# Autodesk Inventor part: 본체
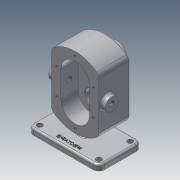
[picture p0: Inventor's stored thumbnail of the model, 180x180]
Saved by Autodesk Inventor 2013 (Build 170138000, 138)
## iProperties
Created: 2019-03
Part Number: 본체
Material: 알루미늄 6061
Document SubType Name: Modeling
Designer: Administrator
Density: 2.71 g/cm^3
Mass: 1191.13 g
Surface Area: 720.144 cm^2
Volume: 439.532 cm^3
Author: Administrator
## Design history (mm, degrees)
sketch "스케치1"
  geometry: L1 (-40, 44.721)-(-40, -44.721); L2 (40, 44.721)-(40, -44.721); A1 r 60 centre (0, 0) between (-40, -44.721) and (40, -44.721); A2 r 60 centre (0, 0) between (40, 44.721) and (-40, 44.721); 1 further point
  constraints: 4 end point, 4 point on circle, 2 centre point, 1 coincident, 1 parallel, 1 vertical
  dimensions: "d1" = 40 distance from line of A1.centre L1; "d2" = 40 distance from line of L2 point (0, 0); "d3" = 60 radius of A2; "d4" = 60 radius of A1
extrude "돌출1" new body sketch "스케치1" stored distance "d5" = 53; taper "d6" = 0 deg
sketch "스케치2"
  geometry: L1 (40, -44.721)-(40, 44.721) reference; L2 (0, 0)-(0, 78); L3 (60, 68)-(-60, 68); L4 (-60, 68)-(-60, 78); L5 (-60, 78)-(60, 78); L6 (60, 78)-(60, 68); A1 r 60 centre (0, 0) between (40, 44.721) and (-40, 44.721) reference
  constraints: 10 end point, 3 parallel, 1 horizontal, 1 midpoint, 1 perpendicular
  dimensions: "d7" = 78 distance of L2.end L2.start; "d8" = 120 distance of L4.end L5.end; "d9" = 10 distance of L3.end L4.end
extrude "돌출2" join sketch "스케치2" distance "d10" = 73; taper "d11" = 0 deg
sketch "스케치3"
  geometry: L1 (120, 0)-(0, 0) reference; L2 (54, 0)-(66, 0); L3 (66, 0)-(66, -43); L4 (66, -43)-(54, -43); L5 (54, -43)-(54, 0); 2 further points
  constraints: 8 end point, 2 midpoint, 2 parallel, 1 horizontal, 1 perpendicular
  dimensions: "d12" = 12 distance of L3.end L4.end; "d13" = 43 distance of L2.end L3.end
extrude "돌출3" join sketch "스케치3" stored distance "d14" = 73; taper "d15" = 0 deg
sketch "스케치4"
  geometry: L1 (-40, 44.721)-(-40, -44.721) reference; L2 (0, 0)-(0, -22); L3 (0, 0)-(0, 22); L4 (24, -22)-(24, 22); L5 (-24, -22)-(-24, 22); A1 r 60 centre (0, 0) between (-40, -44.721) and (40, -44.721) reference; A2 r 24 centre (0, -22) between (24, -22) and (-24, -22); A3 r 24 centre (0, 22) between (24, 22) and (-24, 22)
  constraints: 8 end point, 4 point on circle, 3 tangent, 2 centre point, 2 coincident, 2 parallel, 1 collinear
  dimensions: "d16" = 22 distance of L2.start L2.end; "d17" = 22 distance of L2.start L3.end; "d18" = 48 diameter of A2; "d19" = 48 diameter of A3
extrude "돌출4" cut sketch "스케치4" distance "d20" = 29; taper "d21" = 0 deg
sketch "스케치5"
  geometry: C1 r 12.5 at (0, 22); A1 r 24 centre (0, 22) between (24, 22) and (-24, 22) reference; 1 further point
  constraints: 1 centre point, 1 coincident
  dimensions: "d22" = 25 diameter of C1
extrude "돌출5" cut sketch "스케치5" distance "d23" = 15; taper "d24" = 0 deg
sketch "스케치6"
  geometry: C1 r 12.5 at (0, -22); A1 r 24 centre (0, -22) between (-24, -22) and (24, -22) reference; 1 further point
  constraints: 1 centre point, 1 coincident
  dimensions: "d25" = 25 diameter of C1
extrude "돌출6" cut sketch "스케치6" distance "d26" = 15; taper "d27" = 0 deg
sketch "스케치7"
  geometry: L1 (6, 68)-(6, 59.699) reference; L2 (0, 0)-(0, -22); C1 r 19 at (0, -22); A1 r 60 centre (0, 0) between (40, 44.721) and (6, 59.699) reference
  constraints: 2 end point, 1 centre point, 1 coincident, 1 parallel
  dimensions: "d28" = 22 distance of L2.start L2.end; "d29" = 38 diameter of C1
extrude "돌출7" join sketch "스케치7" distance "d30" = 17; taper "d31" = 0 deg
sketch "스케치8"
  geometry: C1 r 19 at (0, 0) reference; C2 r 14 at (0, 0); 1 further point
  constraints: 1 centre point, 1 coincident
  dimensions: "d32" = 28 diameter of C2
extrude "돌출8" cut sketch "스케치8" distance "d33" = 7.3; taper "d34" = 0 deg
sketch "스케치9"
  geometry: C1 r 14 at (0, 0) reference; C2 r 8.5 at (0, 0); 1 further point
  constraints: 1 centre point, 1 coincident
  dimensions: "d35" = 17 diameter of C2
extrude "돌출9" cut sketch "스케치9" stored distance "d36" = 7.3; taper "d37" = 0 deg
fillet "모깎기1" dims "d38" = 10
sketch "스케치10"
  geometry: A1 r 24 centre (0, 22) between (24, 22) and (-24, 22) reference; A2 r 24 centre (0, -22) between (-24, -22) and (24, -22) reference; A3 r 31 centre (0, -22) between (0, -53) and (31, -22); A4 r 31 centre (0, 22) between (-31, 22) and (31, 22); 2 further points
  constraints: 6 point on circle, 2 centre point, 2 coincident
  dimensions: "d39" = 62 diameter of A3; "d40" = 62 diameter of A4
hole "구멍1" sketch "스케치10" at (0, -53), (31, -22), (-31, -22), (-31, 22), (31, 22), (0, 53) diameter "d41" = 4.134; stored, may be unused: countersink angle "d45" = 90 deg, drill point angle "d47" = 118 deg; dims "d42" = 10, "d43" = 4, "d44" = 2, "d46" = 12
sketch "스케치11"
  geometry: L1 (53, 89.443)-(53, 0) reference; L2 (10, 122.721)-(63, 122.721) reference; C1 r 11 at (39, 44.721); 1 further point
  constraints: 1 centre point
  dimensions: "d48" = 22 diameter of C1; "d49" = 78 distance from line of C1.centre L2; "d50" = 14 distance from line of C1.centre L1
extrude "돌출10" join sketch "스케치11" distance "d51" = 8; taper "d52" = 0 deg
sketch "스케치12"
  geometry: C1 r 11 at (0, 0) reference; 2 further points
  constraints: 1 coincident
hole "구멍2" sketch "스케치12" at (0, 0) diameter "d53" = 8.376; stored, may be unused: countersink angle "d57" = 90 deg, drill point angle "d59" = 118 deg; dims "d54" = 10, "d55" = 4, "d56" = 2, "d58" = 12
sketch "스케치13"
  geometry: C1 r 4.5 at (-44, 33); C2 r 4.5 at (56, 33); C3 r 4.5 at (56, -20); C4 r 4.5 at (-44, -20); A1 r 10 centre (-44, 33) between (-44, 43) and (-54, 33) reference; A2 r 10 centre (-44, -20) between (-54, -20) and (-44, -30) reference; A3 r 10 centre (56, -20) between (56, -30) and (66, -20) reference; A4 r 10 centre (56, 33) between (66, 33) and (56, 43) reference; 1 further point
  constraints: 4 centre point, 4 coincident
  dimensions: "d60" = 9 diameter of C1; "d61" = 9 diameter of C2; "d62" = 9 diameter of C3; "d63" = 9 diameter of C4
extrude "돌출11" cut sketch "스케치13" stored distance "d64" = 8; taper "d65" = 0 deg
fillet "모깎기2" dims "d66" = 10
chamfer "모따기1" distance "d67" = 1; stored, may be unused: second distance "d68" = 2, angle "d69" = 45 deg
chamfer "모따기2" distance "d70" = 0.7; stored, may be unused: second distance "d71" = 2, angle "d72" = 30 deg
fillet "모깎기3" dims "d73" = 0.5
fillet "모깎기4" dims "d74" = 3
fillet "모깎기5" dims "d75" = 3
fillet "모깎기6" dims "d76" = 3
fillet "모깎기7" dims "d77" = 3
fillet "모깎기8" dims "d78" = 3
sketch "스케치14"
  geometry: L1 (-10, 60)-(-10, 7) reference; A1 r 7 centre (0, 7) between (-7, 7) and (0, 0) reference; 2 further points
  constraints: 1 horizontal alignment, 1 other
  dimensions: "d79" = 60 distance from line of point (50, 7) L1
feature "엠보싱1" sketch "스케치14" dims "d80" = 0.5, "d81" = 0
fillet "모깎기9" dims "d82" = 3
node "솔리드1"
mirror "대칭1"
